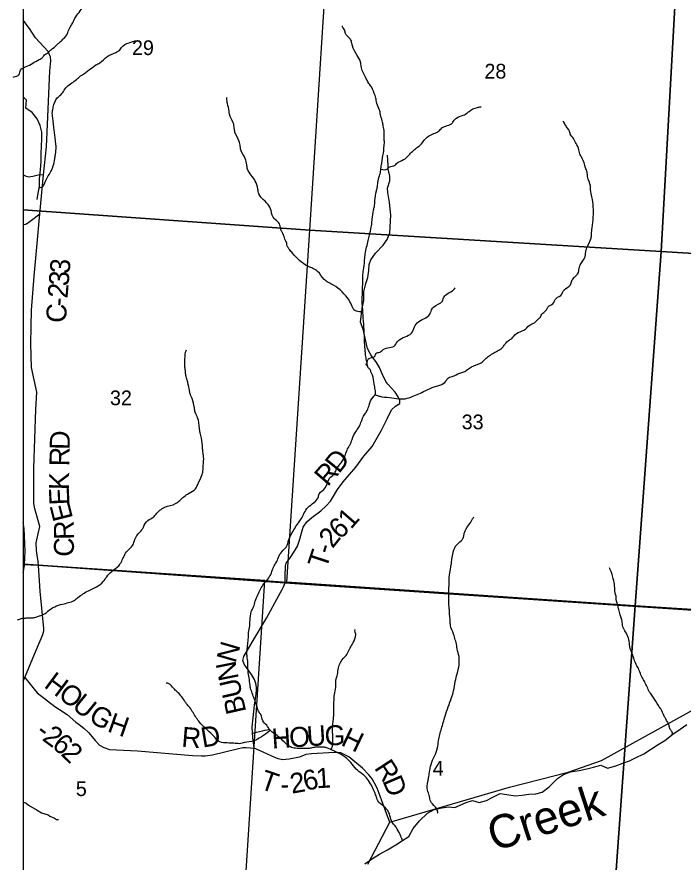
# Model space of a CAD drawing. Extents: x -13.1 to 43.1, y 0 to 22.
# Drawn here: x 2.082 to 3.976, y 16.37 to 18.772 of the extents above; entities that cross this region are included whole.
import ezdxf

# ---------------------------------------------------------------- set-up
doc = ezdxf.new("R2010")
doc.units = 0
for name, color, linetype in [('GM_X_Corporation', 7, 'Continuous'), ('GM_X_County_Road', 7, 'Continuous'), ('GM_X_County_Road_Text', 7, 'Continuous'), ('GM_X_Minor_River', 7, 'Continuous'), ('GM_X_Minor_River_Text', 7, 'Continuous'), ('GM_X_Section_Text', 7, 'Continuous'), ('GM_X_Township_Road', 7, 'Continuous'), ('GM_X_Township_Road_Text', 7, 'Continuous'), ('SH_Data', 7, 'Continuous')]:
    doc.layers.add(name, color=color, linetype=linetype)

msp = doc.modelspace()

# ---------------------------------------------------------------- linework, layer by layer
at = {"layer": 'GM_X_Corporation'}
for points in [[(7.0807, 20.9), (2.1, 20.9), (2.1, 14.1), (6.6193, 14.1), (6.6994, 15.2069), (6.7531, 15.956), (6.8236, 16.9075), (6.9509, 19.0179), (7.0108, 19.8446), (7.0164, 19.8954), (7.0617, 20.6133)], [(7.0804, 20.9), (2.1, 20.9), (2.1, 14.1), (6.619, 14.1), (6.6992, 15.2074), (6.7528, 15.9566), (6.8234, 16.908), (6.8365, 17.1257), (6.9507, 19.0184), (6.9616, 19.1692), (7.0106, 19.8452), (7.0162, 19.896), (7.0615, 20.6138)], [(7.0804, 20.9), (2.1, 20.9), (2.1, 17.2152), (2.1437, 17.2135), (2.8442, 17.1637), (3.8328, 17.0966), (4.4304, 17.0575), (6.8234, 16.908), (6.8365, 17.1257), (6.9507, 19.0184), (6.9616, 19.1692), (7.0106, 19.8452), (7.0162, 19.896), (7.0615, 20.6138)], [(2.1, 19.2176), (2.1, 18.2234), (2.9147, 18.1656), (2.978, 19.1575)], [(2.978, 19.1575), (3.9684, 19.0905), (3.9134, 18.1046), (2.9147, 18.1656)], [(3.9684, 19.0905), (4.9602, 19.0234), (4.9031, 18.044), (3.9134, 18.1046)], [(2.1, 18.2234), (2.1, 17.2165), (2.7867, 17.1698), (2.8499, 17.1651), (2.9147, 18.1656)], [(2.9147, 18.1656), (3.9134, 18.1046), (3.8395, 17.0976), (2.8499, 17.1651)], [(4.9031, 18.044), (4.8272, 17.0344), (3.8395, 17.0976), (3.9134, 18.1046)], [(2.1, 17.2165), (2.1, 16.2245), (2.7236, 16.1815), (2.7867, 17.1698)], [(2.1, 17.2152), (2.1, 14.1), (6.619, 14.1), (6.6992, 15.2074), (6.7528, 15.9566), (6.8234, 16.908), (4.4304, 17.0575), (3.8328, 17.0966), (2.8442, 17.1637), (2.1437, 17.2135)], [(2.8499, 17.1651), (3.8395, 17.0976), (3.7693, 16.1222), (2.7236, 16.1815), (2.7867, 17.1698)], [(3.8395, 17.0976), (4.8272, 17.0344), (4.7589, 16.0643), (3.7693, 16.1222)]]:
    msp.add_lwpolyline(points, close=True, dxfattribs=at)
at = {"layer": 'GM_X_County_Road'}
msp.add_line((2.1, 16.884), (2.1049, 16.8946), dxfattribs=at)
for points in [[(2.1393, 17.2423), (2.1373, 17.2552), (2.1364, 17.2769), (2.1421, 17.3022), (2.1473, 17.3238), (2.1329, 17.3738), (2.1304, 17.389), (2.1303, 17.4896), (2.1326, 17.5723), (2.1357, 17.6562), (2.1383, 17.7055), (2.1233, 17.7756), (2.1212, 17.8421), (2.123, 17.8922), (2.1237, 17.9385), (2.1315, 18.0352), (2.1387, 18.1175), (2.1469, 18.2123), (2.1575, 18.3227), (2.1658, 18.4019), (2.1704, 18.4876), (2.176, 18.6186), (2.1783, 18.647), (2.1773, 18.6577), (2.1751, 18.6641), (2.1707, 18.6737), (2.1345, 18.7125), (2.1178, 18.739), (2.1, 18.7623)], [(2.1049, 16.8946), (2.1273, 16.9493), (2.1556, 17.0169), (2.1588, 17.0267), (2.1585, 17.0336), (2.1482, 17.1397), (2.1439, 17.213), (2.1422, 17.2244), (2.1393, 17.2423)], [(3.0801, 16.364), (3.1423, 16.4836), (3.4823, 16.5823), (3.6492, 16.6255), (3.7439, 16.658), (4.1556, 16.8859)]]:
    msp.add_lwpolyline(points, dxfattribs=at)
at = {"layer": 'GM_X_Minor_River'}
for points in [[(2.1397, 18.2528), (2.1421, 18.271), (2.1461, 18.2892), (2.1462, 18.3112), (2.1495, 18.337), (2.1512, 18.3605), (2.1514, 18.384), (2.1523, 18.4037), (2.1532, 18.4257), (2.1526, 18.4439), (2.1482, 18.4629), (2.1401, 18.482), (2.1258, 18.4995), (2.107, 18.5126), (2.1094, 18.5346), (2.1, 18.5446)], [(2.1, 17.1922), (2.1008, 17.1954), (2.104, 17.2136), (2.1049, 17.2349), (2.1051, 17.2523), (2.1045, 17.2751), (2.1039, 17.2971), (2.1026, 17.3176), (2.1, 17.3347)], [(3.1966, 16.442), (3.2086, 16.4648), (3.2262, 16.4866), (3.2491, 16.5085), (3.2688, 16.5189), (3.2901, 16.5241), (3.3098, 16.5269), (3.3272, 16.5253), (3.3591, 16.5387), (3.3773, 16.5446), (3.3962, 16.5391), (3.4174, 16.545), (3.4349, 16.554), (3.4562, 16.5644), (3.4751, 16.562), (3.4986, 16.558), (3.519, 16.5601), (3.5372, 16.563), (3.5577, 16.5636), (3.5759, 16.5688), (3.5949, 16.5838), (3.6186, 16.6071), (3.6361, 16.6184), (3.6558, 16.6258), (3.6808, 16.6301), (3.7028, 16.6345), (3.721, 16.6397), (3.7423, 16.6448), (3.7611, 16.6363), (3.7847, 16.6429), (3.8044, 16.6511), (3.8234, 16.6578), (3.8409, 16.666), (3.8644, 16.6772), (3.9055, 16.7042), (3.9238, 16.7154), (3.9467, 16.7334), (3.968, 16.7477), (3.987, 16.7612)], [(2.1, 16.5403), (2.1077, 16.5377), (2.1148, 16.5319), (2.1397, 16.5176), (2.1517, 16.5098), (2.1709, 16.5039), (2.1758, 16.5004), (2.189, 16.4942), (2.1942, 16.4911), (2.1999, 16.4906)], [(3.0714, 16.3652), (3.0928, 16.3795), (3.1134, 16.3923), (3.1355, 16.4044), (3.1592, 16.4187), (3.1783, 16.4315), (3.1966, 16.442)]]:
    msp.add_lwpolyline(points, dxfattribs=at)
for points in [[(2.0714, 18.6008), (2.0885, 18.6082), (2.0923, 18.6203), (2.1086, 18.6303), (2.145, 18.6502), (2.1556, 18.6572), (2.1583, 18.6613), (2.1697, 18.6691), (2.1754, 18.6751), (2.1837, 18.6814), (2.1997, 18.6959), (2.2062, 18.7019), (2.2149, 18.7101), (2.2259, 18.7243), (2.2279, 18.7307), (2.2409, 18.7547), (2.2493, 18.772), (2.2619, 18.7884), (2.2818, 18.8244), (2.2928, 18.8375), (2.3115, 18.8664), (2.3203, 18.8795), (2.329, 18.8888), (2.3435, 18.9056), (2.3503, 18.9108), (2.3579, 18.9171), (2.364, 18.9272), (2.369, 18.934), (2.38, 18.9524), (2.3869, 18.9598), (2.3972, 18.9725), (2.4087, 18.9951), (2.4163, 19.0055), (2.4296, 19.0265), (2.4369, 19.0336), (2.446, 19.0441), (2.4536, 19.0587), (2.4586, 19.0651), (2.4685, 19.0789), (2.475, 19.0841), (2.4863, 19.0915), (2.4996, 19.103), (2.5141, 19.1161), (2.5235, 19.1193), (2.5303, 19.1196), (2.5341, 19.1196), (2.5428, 19.1202), (2.5707, 19.1209), (2.5881, 19.1199), (2.6043, 19.1193)], [(3.0797, 17.7778), (3.0783, 17.7835), (3.0754, 17.799), (3.0739, 17.807), (3.0725, 17.821), (3.0704, 17.8464), (3.0701, 17.857), (3.0695, 17.8747), (3.0674, 17.9065), (3.0664, 17.9198), (3.0654, 17.9406), (3.064, 17.955), (3.0642, 17.9818), (3.0647, 17.9988), (3.0656, 18.0238), (3.0657, 18.0329), (3.0665, 18.0468), (3.0701, 18.071), (3.0705, 18.0808), (3.0725, 18.0978), (3.0807, 18.1362), (3.0842, 18.1513), (3.0897, 18.1736), (3.0909, 18.1822), (3.0921, 18.197), (3.096, 18.2226), (3.0984, 18.2328), (3.1, 18.2498), (3.1043, 18.277), (3.1063, 18.2864), (3.1083, 18.3007), (3.113, 18.3203), (3.1149, 18.3263), (3.1165, 18.3362), (3.1188, 18.3524), (3.12, 18.3584), (3.1212, 18.3686), (3.124, 18.3841), (3.1248, 18.3905), (3.1256, 18.4007), (3.1268, 18.4173), (3.1265, 18.4241), (3.1266, 18.4355), (3.1252, 18.4532), (3.1237, 18.4608), (3.1219, 18.4722), (3.1164, 18.4897), (3.1153, 18.4965), (3.1131, 18.5067), (3.1053, 18.5258), (3.1039, 18.5341), (3.1002, 18.5478), (3.0898, 18.5725), (3.0827, 18.5828), (3.073, 18.6003), (3.0607, 18.6307), (3.0593, 18.6429), (3.0496, 18.6619), (3.0359, 18.6897), (3.0337, 18.6984), (3.0292, 18.7095), (3.0161, 18.7248), (3.015, 18.7293), (3.0098, 18.7404), (3.0075, 18.7434), (3.0061, 18.7465)], [(2.1453, 18.2857), (2.1565, 18.2908), (2.1615, 18.3002), (2.1653, 18.3088), (2.1775, 18.3302), (2.1821, 18.3399), (2.1852, 18.3486), (2.1899, 18.3682), (2.1915, 18.3803), (2.1931, 18.3912), (2.1921, 18.4177), (2.1903, 18.434), (2.1882, 18.4491), (2.1839, 18.4844), (2.1829, 18.5018), (2.1856, 18.5154), (2.1967, 18.5413), (2.207, 18.5506), (2.2268, 18.576), (2.2416, 18.5864), (2.2663, 18.6061), (2.2777, 18.6139), (2.2875, 18.6209), (2.3069, 18.635), (2.3175, 18.6413), (2.338, 18.658), (2.363, 18.6709), (2.3759, 18.679), (2.3797, 18.685), (2.4009, 18.6983), (2.4112, 18.702), (2.4191, 18.7041)], [(3.0657, 17.9335), (3.0472, 17.9352), (3.0386, 17.9413), (3.0356, 17.9486), (3.0263, 17.9665), (2.9817, 18.0095), (2.9554, 18.0257), (2.937, 18.0483), (2.9092, 18.063), (2.8657, 18.1003), (2.857, 18.1103), (2.8518, 18.1179), (2.8481, 18.1316), (2.8455, 18.1366), (2.8429, 18.1438), (2.8366, 18.1594), (2.8329, 18.1666), (2.83, 18.1799), (2.8086, 18.2059), (2.8057, 18.2169), (2.7986, 18.2352), (2.7702, 18.2685), (2.7669, 18.2825), (2.7599, 18.3049), (2.7378, 18.3392), (2.7356, 18.3514), (2.7312, 18.3692), (2.7186, 18.3943), (2.7171, 18.4034), (2.7142, 18.4179), (2.7019, 18.4445), (2.7001, 18.4547), (2.6972, 18.471), (2.6864, 18.495), (2.6857, 18.5041), (2.6806, 18.5253), (2.6795, 18.5318), (2.6792, 18.5397), (2.6796, 18.5435)], [(3.1168, 18.3385), (3.1361, 18.34), (3.1407, 18.3445), (3.1577, 18.3503), (3.1615, 18.3548), (3.1816, 18.3659), (3.1892, 18.3714), (3.1964, 18.3785), (3.2181, 18.3994), (3.2298, 18.4079), (3.2397, 18.421), (3.2674, 18.4403), (3.2811, 18.4465), (3.2902, 18.4562), (3.3201, 18.4701), (3.3236, 18.4754), (3.3319, 18.4843), (3.3611, 18.4976), (3.3675, 18.5031), (3.3914, 18.5145), (3.4016, 18.5163)], [(3.1013, 17.7014), (3.1003, 17.6992), (3.1048, 17.6965), (3.1135, 17.6934), (3.141, 17.69), (3.1682, 17.6862), (3.192, 17.6877), (3.2109, 17.6946), (3.2469, 17.7111), (3.2628, 17.7185), (3.3018, 17.7368), (3.3064, 17.744), (3.3193, 17.7494), (3.3416, 17.7593), (3.353, 17.763), (3.3628, 17.7692), (3.3878, 17.7829), (3.4018, 17.7884), (3.4132, 17.7988), (3.4383, 17.8166), (3.4641, 17.834), (3.4706, 17.843), (3.4801, 17.8523), (3.4903, 17.859), (3.4975, 17.8679), (3.5187, 17.879), (3.5278, 17.8845), (3.543, 17.8975), (3.5514, 17.9012), (3.559, 17.9079), (3.5673, 17.9153), (3.5707, 17.9183), (3.573, 17.9236), (3.5826, 17.9344), (3.5875, 17.9393), (3.5917, 17.9471), (3.6088, 17.9597), (3.6107, 17.9646), (3.6153, 17.9718), (3.6316, 17.9836), (3.6335, 17.9881), (3.6381, 17.996), (3.6559, 18.0101), (3.6579, 18.0161), (3.6625, 18.0267), (3.6785, 18.0457), (3.68, 18.0536), (3.6839, 18.0672), (3.6976, 18.0901), (3.6988, 18.0995), (3.7023, 18.1153), (3.7146, 18.1428), (3.7158, 18.1541), (3.7175, 18.1726), (3.7207, 18.2028), (3.7209, 18.2319), (3.7169, 18.26), (3.7133, 18.2801), (3.7126, 18.2906), (3.7045, 18.3176), (3.7031, 18.3305), (3.6986, 18.343), (3.6894, 18.3696), (3.6838, 18.3792), (3.6797, 18.3936), (3.6719, 18.4122), (3.6682, 18.418), (3.6649, 18.4259), (3.6551, 18.4386), (3.6544, 18.4427), (3.6518, 18.4496), (3.6447, 18.4591), (3.6432, 18.4618), (3.6372, 18.4721), (3.6358, 18.4751)], [(3.0797, 17.7778), (3.0756, 17.7862), (3.0779, 17.7899), (3.0795, 17.7967), (3.0856, 17.8019), (3.1007, 17.8085), (3.1034, 17.8149), (3.1144, 17.8193), (3.1235, 17.8263), (3.1576, 17.8391), (3.1614, 17.8451), (3.1709, 17.8552), (3.2065, 17.8762), (3.2104, 17.886), (3.2203, 17.9021), (3.2559, 17.9273), (3.2594, 17.9356), (3.2663, 17.9472), (3.2917, 17.9639), (3.294, 17.9703), (3.3005, 17.9811), (3.3202, 17.9933), (3.3282, 18.0012)], [(2.0833, 17.0581), (2.0955, 17.062), (2.1065, 17.0633), (2.1197, 17.0639), (2.131, 17.0645), (2.1359, 17.0659), (2.1461, 17.0696), (2.1628, 17.0761), (2.1704, 17.0828), (2.2117, 17.103), (2.2446, 17.1135), (2.2556, 17.1217), (2.2852, 17.1409), (2.3276, 17.1668), (2.3375, 17.1807), (2.352, 17.196), (2.3714, 17.2119), (2.3867, 17.2393), (2.3962, 17.2547), (2.411, 17.2692), (2.4153, 17.2805), (2.4267, 17.303), (2.4374, 17.3135), (2.4416, 17.3217), (2.4546, 17.3405), (2.4701, 17.3504), (2.4777, 17.3587), (2.502, 17.378), (2.5334, 17.3885), (2.5566, 17.4082), (2.5714, 17.4178), (2.5896, 17.4308), (2.5961, 17.4432), (2.6087, 17.4714), (2.6115, 17.4853), (2.6119, 17.4963), (2.6129, 17.5216), (2.6107, 17.5352), (2.61, 17.5466), (2.6068, 17.5742), (2.6031, 17.5894), (2.6013, 17.6023), (2.5959, 17.6326), (2.5892, 17.6479), (2.5866, 17.6604), (2.58, 17.6873), (2.5741, 17.7021), (2.5719, 17.7143), (2.566, 17.7397), (2.5624, 17.753), (2.5613, 17.7636), (2.5599, 17.7761), (2.5597, 17.7973), (2.5601, 17.8044), (2.5613, 17.8177), (2.5621, 17.8207), (2.5644, 17.8252)], [(3.1783, 16.4315), (3.1568, 16.4733), (3.1493, 16.4828), (3.1426, 16.5015), (3.1333, 16.5205), (3.1063, 16.5474), (3.1041, 16.5546), (3.0993, 16.5675), (3.0922, 16.5835), (3.0687, 16.6163), (3.051, 16.6298), (3.0353, 16.6482), (3.0199, 16.6643), (2.9755, 16.6891), (2.965, 16.6934), (2.9552, 16.6962), (2.9461, 16.6967), (2.9337, 16.6965), (2.9284, 16.6958), (2.9216, 16.6944), (2.9106, 16.6927), (2.8831, 16.6927), (2.8661, 16.6944), (2.8541, 16.7003), (2.8417, 16.7114), (2.8143, 16.7349), (2.8019, 16.7445), (2.7922, 16.7586), (2.7809, 16.7713), (2.7754, 16.7891), (2.7705, 16.7956), (2.7661, 16.8067), (2.7609, 16.8219), (2.7498, 16.8534), (2.7457, 16.8671), (2.7429, 16.8883), (2.7396, 16.908), (2.7387, 16.9364), (2.7376, 16.9458), (2.7362, 16.9587), (2.7363, 16.9704), (2.7383, 16.9897), (2.7391, 16.9972), (2.7403, 17.0097), (2.7404, 17.0218), (2.7439, 17.041), (2.7444, 17.0493), (2.7456, 17.0633), (2.7503, 17.0859), (2.7549, 17.095), (2.7599, 17.1111), (2.7668, 17.1292), (2.784, 17.1603), (2.8046, 17.1888), (2.8092, 17.2016), (2.8153, 17.2147), (2.8226, 17.2275), (2.8295, 17.2444), (2.8516, 17.2724), (2.8543, 17.2837), (2.8628, 17.3021), (2.8822, 17.3336), (2.8906, 17.3452), (2.899, 17.3618), (2.9097, 17.3779), (2.9382, 17.4051), (2.9417, 17.416), (2.9588, 17.4335), (2.9715, 17.4613), (2.9825, 17.471), (2.9901, 17.4845), (3.0023, 17.5025), (3.0061, 17.507), (3.0092, 17.5126), (3.0126, 17.5209), (3.0149, 17.5246), (3.0176, 17.5321), (3.0245, 17.5483), (3.0295, 17.5565), (3.0349, 17.5708), (3.0471, 17.5956), (3.054, 17.6054), (3.0598, 17.6185), (3.0713, 17.6429), (3.0777, 17.6527), (3.0835, 17.6685), (3.0946, 17.6914), (3.0992, 17.6958), (3.1011, 17.6988), (3.1015, 17.7053), (3.1008, 17.7132), (3.0975, 17.7284), (3.0928, 17.7538), (3.0894, 17.761), (3.0861, 17.7694), (3.0809, 17.7751), (3.0797, 17.7778)], [(3.2755, 16.5205), (3.2786, 16.5094), (3.2782, 16.5147), (3.2633, 16.5349), (3.2562, 16.5494), (3.2544, 16.5593), (3.2496, 16.5741), (3.2505, 16.5986), (3.2525, 16.6084), (3.2552, 16.6254), (3.2595, 16.6473), (3.278, 16.6943), (3.2808, 16.7151), (3.2893, 16.749), (3.2994, 16.784), (3.3179, 16.8374), (3.3236, 16.8562), (3.3284, 16.883), (3.3338, 16.9049), (3.3393, 16.9298), (3.3397, 16.9354), (3.3397, 16.9434), (3.339, 16.954), (3.3335, 16.9756), (3.3325, 16.9851), (3.3284, 17.0014), (3.3236, 17.0177), (3.3147, 17.0424), (3.3141, 17.0526), (3.3127, 17.0689), (3.3117, 17.0863), (3.3102, 17.0999), (3.3101, 17.1336), (3.3102, 17.1453), (3.3114, 17.1646), (3.3116, 17.1846), (3.3175, 17.2182), (3.3187, 17.2303), (3.3226, 17.2495), (3.3291, 17.2672), (3.3516, 17.2926), (3.3532, 17.3013), (3.3582, 17.3148), (3.3639, 17.3242), (3.3749, 17.3399), (3.3788, 17.3474), (3.3811, 17.3508)], [(3.9452, 16.7323), (3.9454, 16.7389), (3.9394, 16.7469), (3.9379, 16.7515), (3.9353, 16.7599), (3.9267, 16.7766), (3.9227, 16.7842), (3.9126, 16.8048), (3.9059, 16.8147), (3.8913, 16.8387), (3.8831, 16.8495), (3.8686, 16.8784), (3.8615, 16.891), (3.8481, 16.9214), (3.8414, 16.9344), (3.8306, 16.964), (3.8258, 16.9769), (3.8226, 16.9974), (3.8174, 17.0149), (3.8051, 17.0385), (3.8037, 17.0472), (3.8007, 17.0612), (3.7971, 17.0726), (3.793, 17.0878), (3.7919, 17.0924), (3.7908, 17.1), (3.7864, 17.1114), (3.7861, 17.1204), (3.782, 17.1398), (3.7817, 17.1473), (3.7807, 17.1595), (3.7763, 17.1799), (3.7741, 17.1868), (3.77, 17.1989), (3.7681, 17.2024), (3.767, 17.2058)], [(2.9755, 16.6891), (2.979, 16.6993), (2.9802, 16.7046), (2.9806, 16.7102), (2.98, 16.7288), (2.9797, 16.7382), (2.9798, 16.7549), (2.9826, 16.7828), (2.9831, 16.7945), (2.9832, 16.8134), (2.9857, 16.8508), (2.9889, 16.8719), (2.9898, 16.8901), (2.9933, 16.9025), (2.9964, 16.9221), (3.0109, 16.9495), (3.0201, 16.9596), (3.0277, 16.9746), (3.0354, 16.9885), (3.0446, 17.0096), (3.0447, 17.0201), (3.0435, 17.0228), (3.0436, 17.0307)], [(2.7539, 16.7365), (2.8018, 16.7446), (2.7658, 16.7189), (2.7564, 16.7138), (2.7284, 16.7093), (2.7227, 16.7074), (2.7069, 16.7065), (2.6903, 16.7079), (2.6514, 16.7164), (2.6466, 16.7221), (2.6331, 16.7363), (2.6016, 16.767), (2.5919, 16.78), (2.5736, 16.8086), (2.5646, 16.8197), (2.5455, 16.8457), (2.535, 16.8561), (2.5245, 16.8672), (2.5099, 16.878), (2.5068, 16.878)]]:
    msp.add_spline(points, degree=3, dxfattribs=at)
at = {"layer": 'GM_X_Township_Road'}
for points in [[(2.836, 17.1444), (2.8389, 17.1499), (2.8444, 17.1632), (2.8447, 17.1821), (2.8454, 17.2114), (2.8475, 17.2193), (2.8587, 17.2343), (2.8715, 17.2532), (2.8796, 17.2675), (2.886, 17.2875), (2.892, 17.3087), (2.8959, 17.3215), (2.9064, 17.3366), (2.921, 17.3489), (2.9463, 17.3679), (2.9617, 17.3822), (2.974, 17.3953), (2.9934, 17.4284), (3.0093, 17.4502), (3.0455, 17.4919), (3.0683, 17.5231), (3.0923, 17.5509), (3.1183, 17.5972), (3.1347, 17.6296), (3.1425, 17.6455), (3.1484, 17.656), (3.158, 17.6658), (3.1656, 17.6702), (3.171, 17.6728), (3.1707, 17.6812), (3.1663, 17.6919), (3.1574, 17.7056), (3.1365, 17.728), (3.1305, 17.7356), (3.1202, 17.7574), (3.1125, 17.7754), (3.1047, 17.7899), (3.0887, 17.811), (3.0791, 17.829), (3.0737, 17.8503), (3.0669, 17.8846), (3.0589, 17.9044), (3.064, 17.9435), (3.0685, 17.9658), (3.0688, 17.9912), (3.0741, 18.0143), (3.0796, 18.031), (3.0822, 18.0514), (3.0839, 18.0677), (3.0879, 18.081), (3.1018, 18.1001), (3.1234, 18.123), (3.135, 18.1392), (3.1421, 18.1577), (3.1447, 18.2078), (3.141, 18.2439), (3.1369, 18.2728), (3.1359, 18.2846), (3.1426, 18.3058), (3.1424, 18.3194), (3.1378, 18.3385), (3.1379, 18.3499), (3.1361, 18.3791)], [(2.1, 18.3229), (2.1013, 18.3219), (2.1085, 18.3191), (2.1161, 18.3175), (2.1271, 18.3193), (2.1461, 18.324), (2.1575, 18.3227)], [(2.1, 18.1825), (2.1032, 18.1818), (2.1089, 18.1836), (2.12, 18.191), (2.1469, 18.2123)], [(2.7566, 16.6935), (2.7525, 16.724), (2.751, 16.7532), (2.7533, 16.7794), (2.7576, 16.8154), (2.7626, 16.8472), (2.7635, 16.859), (2.7636, 16.8673), (2.7611, 16.8769), (2.7571, 16.8883), (2.7493, 16.9032), (2.7352, 16.9228), (2.7281, 16.932), (2.7248, 16.9427), (2.7273, 16.954), (2.751, 16.9947), (2.7921, 17.0625), (2.8268, 17.127), (2.836, 17.1444)], [(2.1049, 16.8946), (2.1239, 16.8704), (2.131, 16.8612), (2.14, 16.8512), (2.1899, 16.8122), (2.2034, 16.8029), (2.2245, 16.7893), (2.2496, 16.7677), (2.2594, 16.7603), (2.2725, 16.7507), (2.2864, 16.7368), (2.3043, 16.7149), (2.317, 16.7018), (2.3294, 16.6956), (2.3457, 16.69), (2.4249, 16.6863), (2.5814, 16.6724), (2.6065, 16.6713), (2.6175, 16.6719), (2.638, 16.675), (2.7081, 16.6919), (2.7244, 16.6955), (2.7339, 16.695), (2.7566, 16.6935)], [(3.1423, 16.4836), (3.1331, 16.508), (3.1119, 16.5649), (3.106, 16.5794), (3.099, 16.5939), (3.0924, 16.6066), (3.0827, 16.6177), (3.0643, 16.6369), (3.0253, 16.6686), (3.0027, 16.6799), (2.9932, 16.6816), (2.9849, 16.6809), (2.9196, 16.6773), (2.9036, 16.6752), (2.8853, 16.6679), (2.856, 16.6618), (2.837, 16.6602), (2.8245, 16.663), (2.8068, 16.6704), (2.7819, 16.6822), (2.7713, 16.6869), (2.7566, 16.6935)]]:
    msp.add_lwpolyline(points, dxfattribs=at)
at = {"layer": 'SH_Data'}
msp.add_line((2.1, 20.9), (2.1, 14.1), dxfattribs=at)

# ---------------------------------------------------------------- texts
at = {"layer": 'GM_X_County_Road_Text'}
for s, rotation, p in [('3', 85.0816, (2.2316, 18.0402)), ('3', 85.1024, (2.2286, 18.0053)), ('2', 85.28, (2.2258, 17.9705)), ('-', 85.6558, (2.224, 17.9473)), ('C', 87.0715, (2.2216, 17.9011)), ('D', 88.8925, (2.232, 17.5409)), ('R', 88.8993, (2.2311, 17.4942)), ('K', 88.9508, (2.2298, 17.4267)), ('E', 92.8639, (2.2319, 17.3853)), ('E', 104.2867, (2.242, 17.3471)), ('R', 90.8992, (2.2446, 17.2861)), ('C', 88.4151, (2.2433, 17.2368))]:
    msp.add_text(s, height=0.0568, rotation=rotation, dxfattribs=at).set_placement(p)
at = {"layer": 'GM_X_Minor_River_Text'}
msp.add_text('Creek', height=0.0947, rotation=18.0033, dxfattribs=at).set_placement((3.4387, 16.3992))
at = {"layer": 'GM_X_Section_Text'}
for s, height, p in [('29', 0.04186, (2.4092, 18.6631)), ('28', 0.04186, (3.4113, 18.5964)), ('32', 0.04186, (2.3467, 17.6681)), ('33', 0.04186, (3.3467, 17.5997)), ('4', 0.0419, (3.2642, 16.6154)), ('5', 0.0419, (2.2496, 16.5573))]:
    msp.add_text(s, height=height, rotation=0, dxfattribs=at).set_placement(p)
at = {"layer": 'GM_X_Township_Road_Text'}
for s, rotation, p in [('D', 51.138, (2.9975, 17.4717)), ('R', 49.0905, (2.9656, 17.4347)), ('1', 48.9055, (3.0318, 17.3135)), ('6', 41.0782, (2.9994, 17.2845)), ('2', 51.4491, (2.9795, 17.2591)), ('-', 72.5982, (2.9751, 17.2417)), ('T', 71.8618, (2.9616, 17.2006)), ('N', 74.0056, (2.7033, 16.9332)), ('N', 101.2849, (2.7133, 16.8912)), ('H', 323.3151, (2.1563, 16.8684)), ('U', 102.6756, (2.7242, 16.8428)), ('O', 322.9436, (2.1963, 16.8386)), ('U', 321.0153, (2.2358, 16.8088)), ('B', 102.6702, (2.7345, 16.7973)), ('G', 329.9836, (2.2827, 16.7719)), ('H', 340.6976, (2.3365, 16.742)), ('-', 323.0439, (2.1324, 16.7321)), ('2', 323.4149, (2.1514, 16.7178)), ('R', 355.5268, (2.5487, 16.6977)), ('D', 9.803, (2.6103, 16.6948)), ('H', 3.8131, (2.8081, 16.692)), ('O', 3.8095, (2.858, 16.6953)), ('U', 3.7949, (2.9078, 16.6986)), ('G', 359.9781, (2.9567, 16.7019)), ('H', 334.4972, (3.0003, 16.7034)), ('6', 319.5788, (2.1787, 16.6976)), ('2', 315.5667, (2.2046, 16.6756)), ('R', 303.19, (3.0963, 16.6373)), ('T', 340.966, (2.7693, 16.5795)), ('2', 9.8265, (2.8636, 16.564)), ('6', 14.4116, (2.9029, 16.571)), ('1', 3.6711, (2.934, 16.5793)), ('D', 293.2383, (3.1206, 16.6005)), ('-', 2.0994, (2.8319, 16.5623))]:
    msp.add_text(s, height=0.0568, rotation=rotation, dxfattribs=at).set_placement(p)

doc.saveas('drawing.dxf')
